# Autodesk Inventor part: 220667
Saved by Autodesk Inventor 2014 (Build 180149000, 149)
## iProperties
Shininess: 27.0
Length Units: 11272
Angle Units: 11279
Time Units: 11290
Mass Units: 11286
Length Display Precision: 3
Angle Display Precision: 2
Compacted: True
Category: Hydraulics
Company: Autodesk, Inc.
Created: 2001-05
Part Number: 220667
Material: Steel, Mild
Description: FITTING; ST-B40-Q32-S
Document SubType Name: Modeling
Designer: Autodesk, Inc.
Catalog Web Link: http://www.aeroquip.com
Density: 7.86 g/cm^3
Mass: 920.964 g
Surface Area: 271.137 cm^2
Volume: 117.171 cm^3
Appearance: Yellow Zinc
Density: 7.86
Volumn: 7.3241227782804
Area: 41.16363820292827
PropertySet Name: Model Information
Control State: 0
Master: False
Checked Out: True
Last Check In By: JT
Last Check In Date: 2003-06-20
Title: FITTING; ST-B40-Q32-S
Author: Autodesk, Inc.
Comments: SOME DIMENSIONS ARE ESTIMATES
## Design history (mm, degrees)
derived "ST-BQ.ipt"
body "Solid1"
tag "TaggingFeature2"
feature "Solid1::ST-BQ.ipt" dims "ScaleForDerivedMember" = 10
